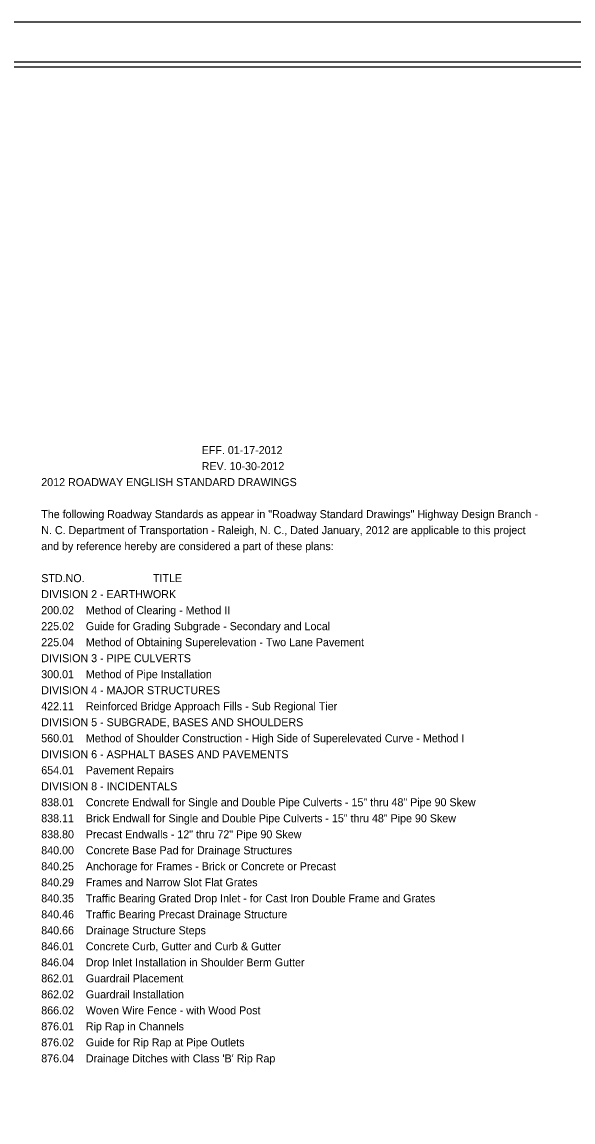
# Model space of a CAD drawing. Extents: x 1974126 to 1975810, y 438878 to 442173.
# Drawn here: x 1975258 to 1975533, y 441624 to 442173 of the extents above; entities that cross this region are included whole.
import ezdxf

# ---------------------------------------------------------------- set-up
doc = ezdxf.new("R2010")
doc.units = 0
for name, color, linetype in [('Default', 7, 'Continuous'), ('Sheet Cutting Line CELL', 7, 'Continuous'), ('Sheet Plan CELL', 7, 'Continuous'), ('Sheet Plot Border Inside CELL', 7, 'Continuous'), ('Sheet Plot Border Outside CELL', 7, 'Continuous')]:
    doc.layers.add(name, color=color, linetype=linetype)

msp = doc.modelspace()

# ---------------------------------------------------------------- linework, layer by layer
at = {"layer": 'Sheet Cutting Line CELL'}
msp.add_line((1975809.14, 442173.29), (1974125.64, 442173.29), dxfattribs=at)
at = {"layer": 'Sheet Plan CELL'}
msp.add_lwpolyline([(1975792.14, 442150.79), (1974292.14, 442150.79), (1974292.14, 441100.79), (1975792.14, 441100.79)], close=True, dxfattribs=at)
at = {"layer": 'Sheet Plot Border Inside CELL'}
msp.add_lwpolyline([(1974138.64, 441098.29), (1975804.64, 441098.29), (1975804.64, 442153.29), (1974138.64, 442153.29)], close=True, dxfattribs=at)
at = {"layer": 'Sheet Plot Border Outside CELL'}
msp.add_lwpolyline([(1974125.64, 441078.29), (1975809.14, 441078.29), (1975809.14, 442173.29), (1974125.64, 442173.29)], close=True, dxfattribs=at)

# ---------------------------------------------------------------- texts
at = {"layer": 'Default'}
for s, p in [('                                                      EFF. 01-17-2012', (1975267.45, 441957.34)), ('                                                      REV. 10-30-2012', (1975267.45, 441949.34)), ('2012 ROADWAY ENGLISH STANDARD DRAWINGS', (1975267.45, 441941.34)), ('The following Roadway Standards as appear in "Roadway Standard Drawings" Highway Design Branch -', (1975267.45, 441925.34)), ('N. C. Department of Transportation - Raleigh, N. C., Dated January, 2012 are applicable to this project', (1975267.45, 441917.34)), ('and by reference hereby are considered a part of these plans:', (1975267.45, 441909.34)), ('STD.NO.                       TITLE', (1975267.45, 441893.34)), ('DIVISION 2 - EARTHWORK', (1975267.45, 441885.34)), ('200.02    Method of Clearing - Method II', (1975267.45, 441877.34)), ('225.02    Guide for Grading Subgrade - Secondary and Local', (1975267.45, 441869.34)), ('225.04    Method of Obtaining Superelevation - Two Lane Pavement', (1975267.45, 441861.34)), ('DIVISION 3 - PIPE CULVERTS', (1975267.45, 441853.34)), ('300.01    Method of Pipe Installation ', (1975267.45, 441845.34)), ('DIVISION 4 - MAJOR STRUCTURES', (1975267.45, 441837.34)), ('422.11    Reinforced Bridge Approach Fills - Sub Regional Tier', (1975267.45, 441829.34)), ('DIVISION 5 - SUBGRADE, BASES AND SHOULDERS', (1975267.45, 441821.34)), ('560.01    Method of Shoulder Construction - High Side of Superelevated Curve - Method I', (1975267.45, 441813.34)), ('DIVISION 6 - ASPHALT BASES AND PAVEMENTS', (1975267.45, 441805.34)), ('654.01    Pavement Repairs', (1975267.45, 441797.34)), ('DIVISION 8 - INCIDENTALS', (1975267.45, 441789.34)), ('838.01    Concrete Endwall for Single and Double Pipe Culverts - 15" thru 48" Pipe 90 Skew', (1975267.45, 441781.34)), ('838.11    Brick Endwall for Single and Double Pipe Culverts - 15" thru 48" Pipe 90 Skew', (1975267.45, 441773.34)), ('838.80    Precast Endwalls - 12" thru 72" Pipe 90 Skew', (1975267.45, 441765.34)), ('840.00    Concrete Base Pad for Drainage Structures', (1975267.45, 441757.34)), ('840.25    Anchorage for Frames - Brick or Concrete or Precast', (1975267.45, 441749.34)), ('840.29    Frames and Narrow Slot Flat Grates', (1975267.45, 441741.34)), ('840.35    Traffic Bearing Grated Drop Inlet - for Cast Iron Double Frame and Grates', (1975267.45, 441733.34)), ('840.46    Traffic Bearing Precast Drainage Structure', (1975267.45, 441725.34)), ('840.66    Drainage Structure Steps', (1975267.45, 441717.34)), ('846.01    Concrete Curb, Gutter and Curb & Gutter', (1975267.45, 441709.34)), ('846.04    Drop Inlet Installation in Shoulder Berm Gutter', (1975267.45, 441701.34)), ('862.01    Guardrail Placement', (1975267.45, 441693.34)), ('862.02    Guardrail Installation', (1975267.45, 441685.34)), ('866.02    Woven Wire Fence - with Wood Post', (1975267.45, 441677.34)), ('876.01    Rip Rap in Channels', (1975267.45, 441669.34)), ('876.02    Guide for Rip Rap at Pipe Outlets', (1975267.45, 441661.34)), ("876.04    Drainage Ditches with Class 'B' Rip Rap", (1975267.45, 441653.34))]:
    msp.add_text(s, height=4, dxfattribs=at).set_placement(p)

doc.saveas('drawing.dxf')
